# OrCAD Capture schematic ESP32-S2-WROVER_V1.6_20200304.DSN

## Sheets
1 01_DesignBlock: title: <ESP32-S2-WROVER>; rev: V1.6; note: <01_Design Block>
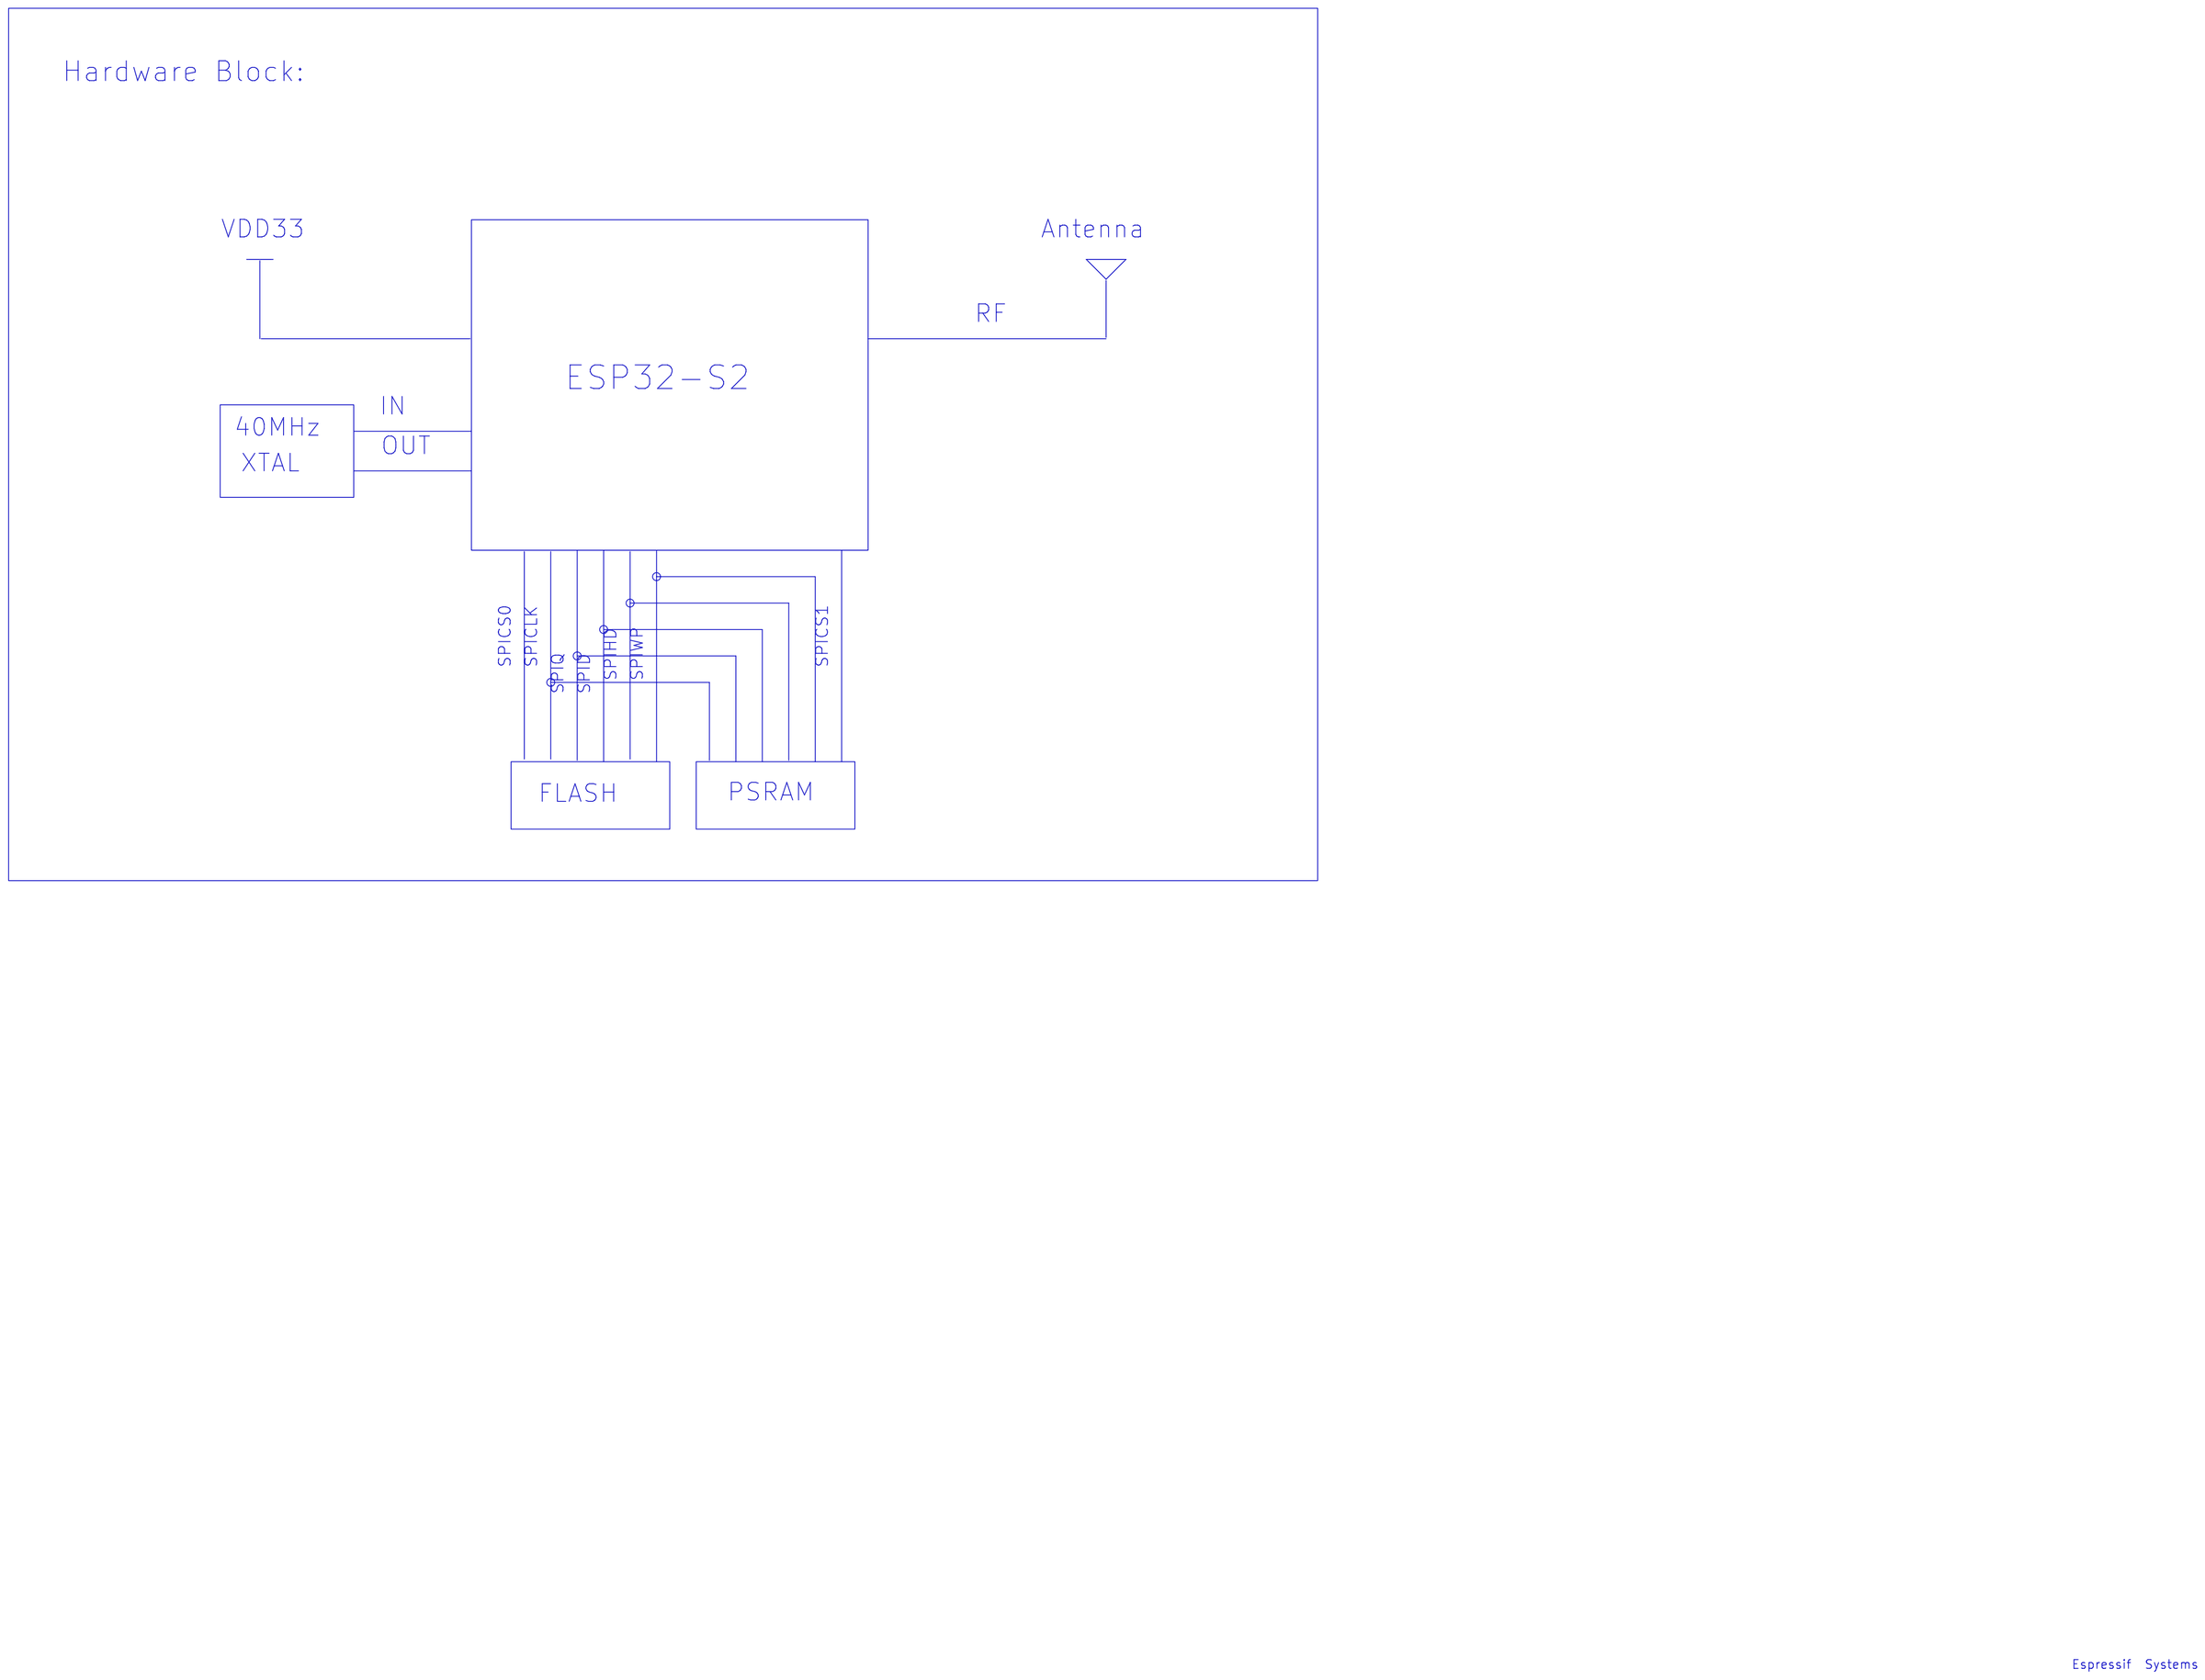
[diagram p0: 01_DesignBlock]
2 02_ESP32-S2-WROVER: size C; note: <02_ESP32-S2-WROVER>
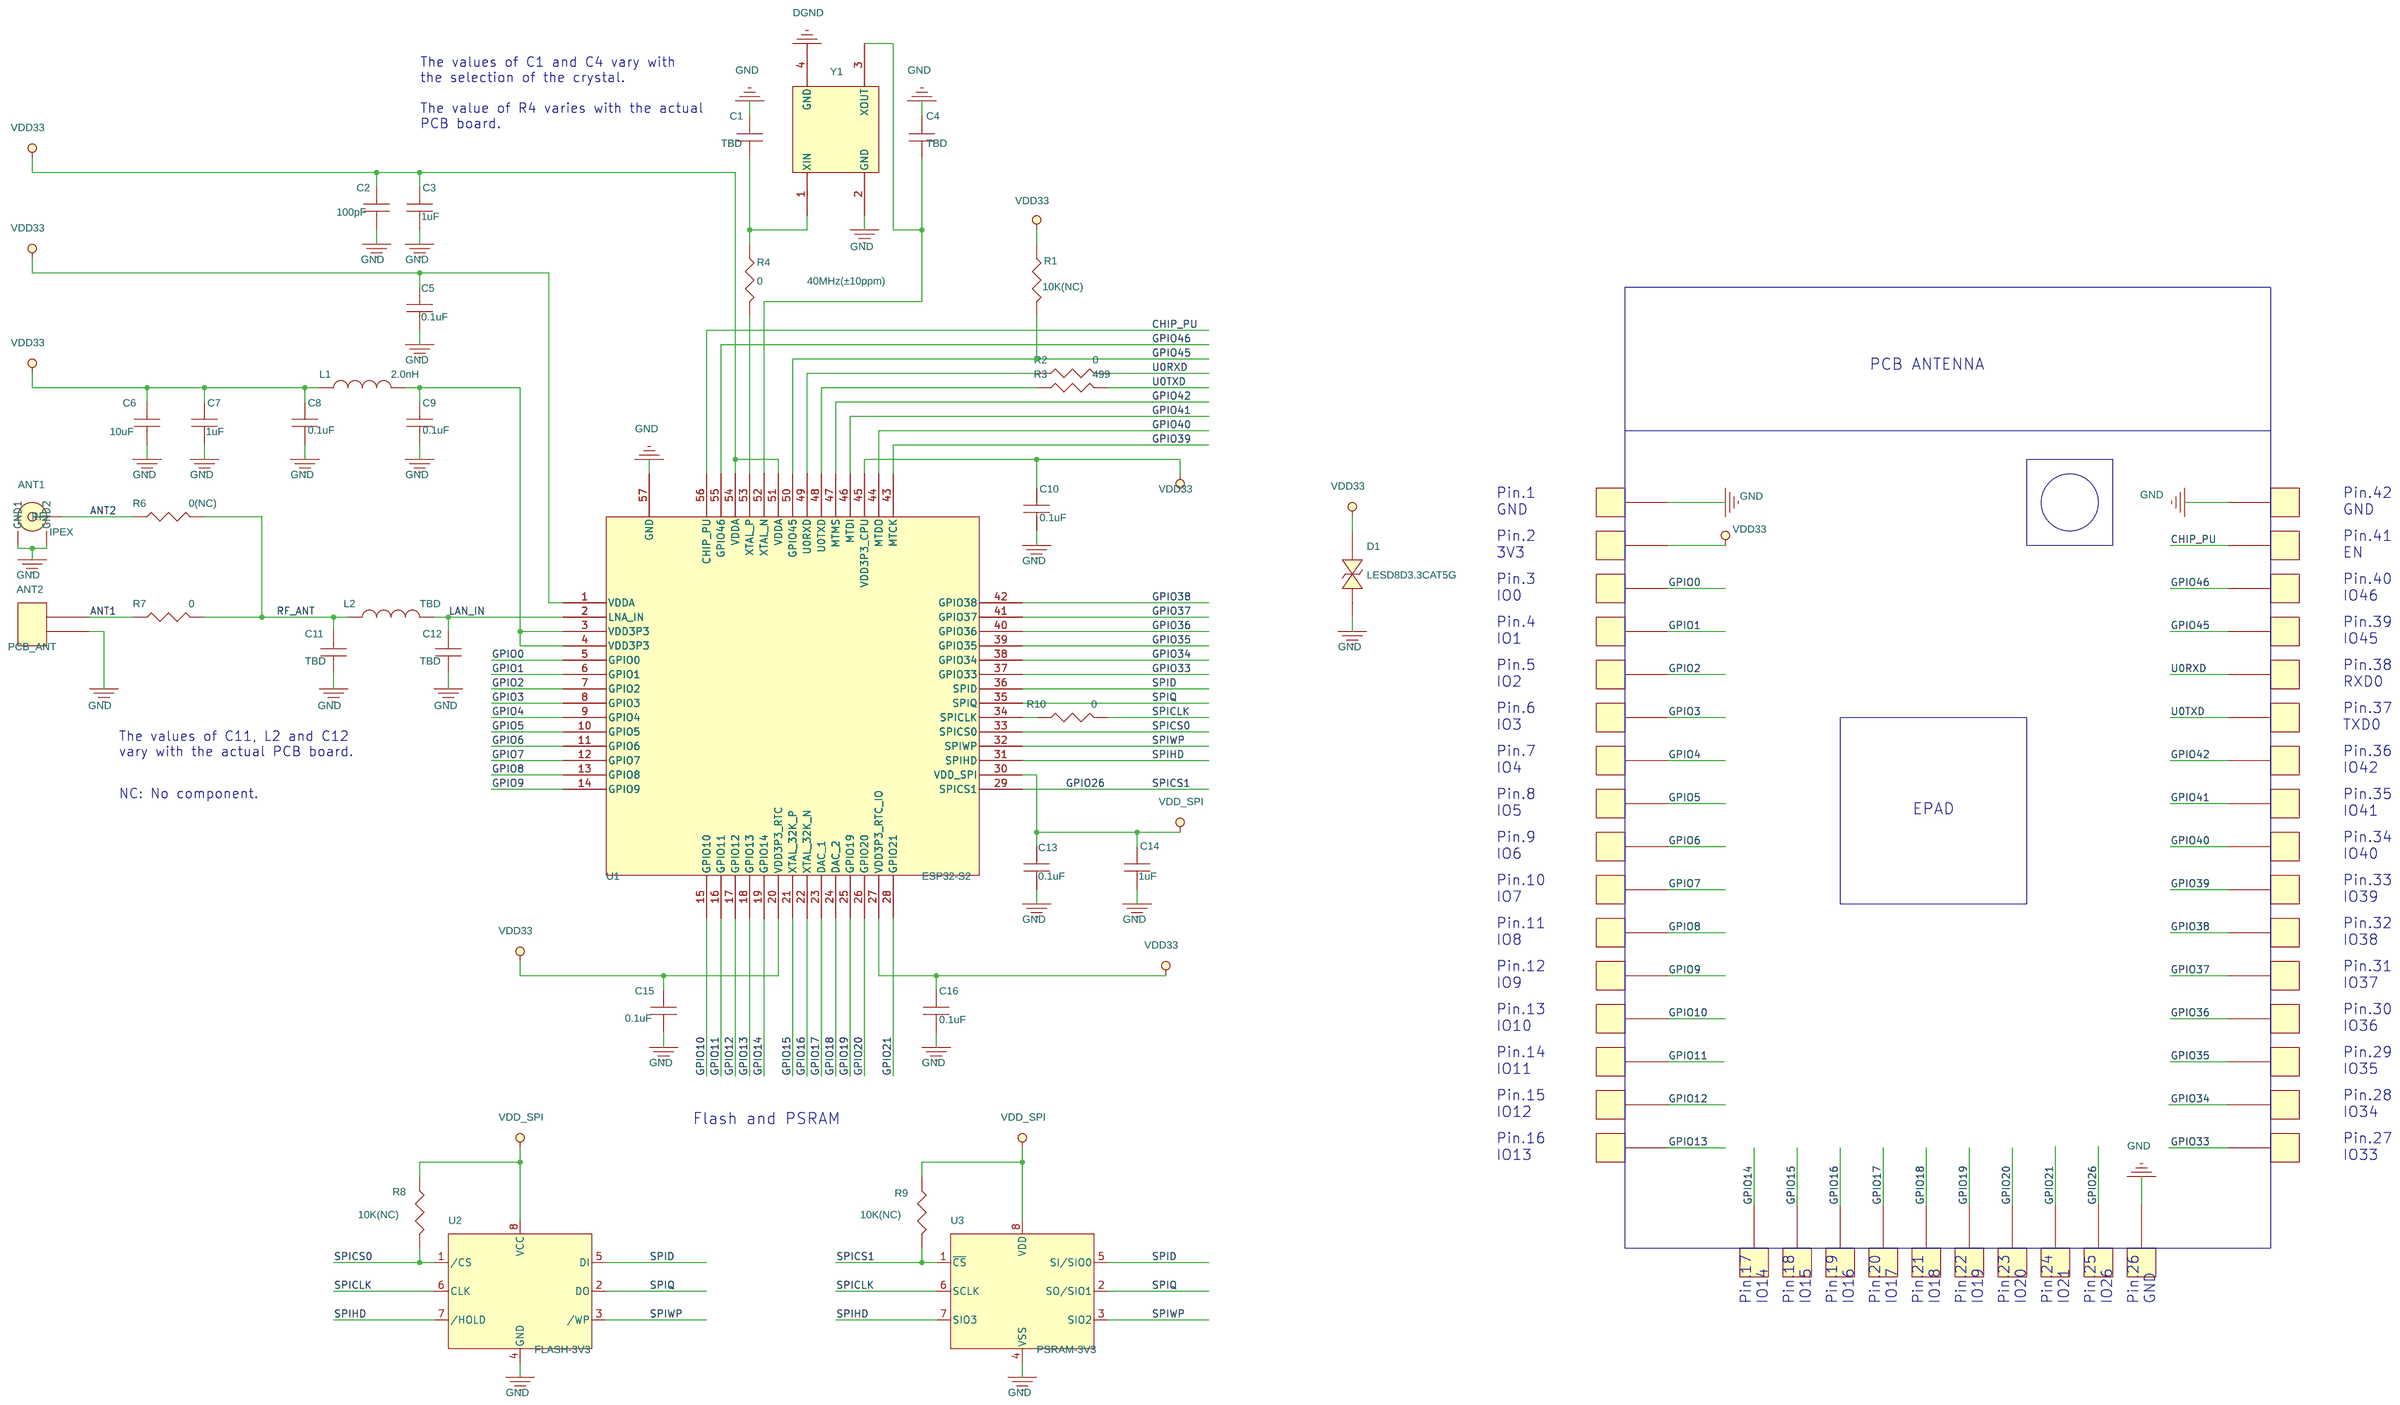
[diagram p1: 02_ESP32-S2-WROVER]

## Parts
ANT1  IPEX  [ECT818000368]
ANT2  PCB_ANT  [MINI_ANT_TYPEB]
C1  TBD  [C0201]
C2  100pF  [C0201]
C3  1uF  [C0201]
C4  TBD  [C0201]
C5  0.1uF  [C0201]
C6  10uF  [C0402]
C7  1uF  [C0201]
C8  0.1uF  [C0201]
C9  0.1uF  [C0201]
C10  0.1uF  [C0201]
C11  TBD  [C0201]
C12  TBD  [C0201]
C13  0.1uF  [C0201]
C14  1uF  [C0201]
C15  0.1uF  [C0201]
C16  0.1uF  [C0201]
D1  LESD8D3.3CAT5G  [SOD882]
J1  CON1  [SPAD_1]
J2  CON1  [SPAD_1]
J3  CON1  [SPAD_1]
J4  CON1  [SPAD_1]
J5  CON1  [SPAD_1]
J6  CON1  [SPAD_1]
J7  CON1  [SPAD_1]
J8  CON1  [SPAD_1]
J9  CON1  [SPAD_1]
J10  CON1  [SPAD_1]
J11  CON1  [SPAD_1]
J12  CON1  [SPAD_1]
J13  CON1  [SPAD_1]
J14  CON1  [SPAD_1]
J15  CON1  [SPAD_1]
J16  CON1  [SPAD_1]
J17  CON1  [SPAD_1]
J18  CON1  [SPAD_1]
J19  CON1  [SPAD_1]
J20  CON1  [SPAD_1]
J21  CON1  [SPAD_1]
J22  CON1  [SPAD_1]
J23  CON1  [SPAD_1]
J24  CON1  [SPAD_1]
J25  CON1  [SPAD_1]
J26  CON1  [SPAD_1]
J27  CON1  [SPAD_1]
J28  CON1  [SPAD_1]
J29  CON1  [SPAD_1]
J30  CON1  [SPAD_1]
J31  CON1  [SPAD_1]
J32  CON1  [SPAD_1]
J33  CON1  [SPAD_1]
J34  CON1  [SPAD_1]
J35  CON1  [SPAD_1]
J36  CON1  [SPAD_1]
J37  CON1  [SPAD_1]
J38  CON1  [SPAD_1]
J39  CON1  [SPAD_1]
J40  CON1  [SPAD_1]
J41  CON1  [SPAD_1]
J42  CON1  [SPAD_1]
L1  2.0nH  [L0201]
L2  TBD  [L0201]
R1  10K(NC)  [R0201]
R2  0  [R0201]
R3  499  [R0201]
R4  0  [R0201]
R6  0(NC)  [R0201A]
R7  0  [R0201A]
R8  10K(NC)  [R0201]
R9  10K(NC)  [R0201]
R10  0  [R0201]
U1  ESP32-S2  [QFN56_0P4_7]
U2  FLASH-3V3  [SOIC08-WN]
U3  PSRAM-3V3  [SOIC-8P]
Y1  40MHz(±10ppm)  [3225]

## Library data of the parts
ANT1 = IPEX_0
ANT2 = CON2
C1-C16 = CAP_NP
D1 = DIODE_BI-DIR_TRIG: Options: ESD
J1-J42 = CON1_1
L1 L2 = CHOKE
R1-R4 R6 R7 R10 = RESISTOR
R8 R9 = RESISTOR_0
U1 = ESP32K
U2 = FLASH_4
U3 = W25Q32_SOIC8_2
Y1 = X1_1

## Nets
GND: ANT1.2(GND1) ANT1.3(GND2) ANT2.2 C1.2 C2.2 C3.2 C4.2 C5.2 C6.2 C7.2 C8.2 C9.2 C10.2 C11.1 C12.1 C13.2 C14.2 C15.2 C16.2 D1.1 J1.1 J26.1 J42.1 U1.57(GND) U2.4(GND) U3.4(VSS) Y1.2(GND) Y1.4(GND)
VDD33: C2.1 C3.1 C5.1 C6.1 C7.1 C8.1 C10.1 C15.1 C16.1 D1.2 J2.1 L1.1 R1.1 U1.1(VDDA) U1.20(VDD3P3_RTC) U1.27(VDD3P3_RTC_IO) U1.45(VDD3P3_CPU) U1.51(VDDA) U1.54(VDDA)
VDD_SPI: C13.1 C14.1 R8.2 R9.2 U1.30(VDD_SPI) U2.8(VCC) U3.8(VDD)
ANT1: ANT2.1 R7.2
ANT2: ANT1.1(RF) R6.1
CHIP_PU: J41.1 U1.56(CHIP_PU)
GPIO0: J3.1 U1.5(GPIO0)
GPIO1: J4.1 U1.6(GPIO1)
GPIO2: J5.1 U1.7(GPIO2)
GPIO3: J6.1 U1.8(GPIO3)
GPIO4: J7.1 U1.9(GPIO4)
GPIO5: J8.1 U1.10(GPIO5)
GPIO6: J9.1 U1.11(GPIO6)
GPIO7: J10.1 U1.12(GPIO7)
GPIO8: J11.1 U1.13(GPIO8)
GPIO9: J12.1 U1.14(GPIO9)
GPIO10: J13.1 U1.15(GPIO10)
GPIO11: J14.1 U1.16(GPIO11)
GPIO12: J15.1 U1.17(GPIO12)
GPIO13: J16.1 U1.18(GPIO13)
GPIO14: J17.1 U1.19(GPIO14)
GPIO15: J18.1 U1.21(XTAL_32K_P)
GPIO16: J19.1 U1.22(XTAL_32K_N)
GPIO17: J20.1 U1.23(DAC_1)
GPIO18: J21.1 U1.24(DAC_2)
GPIO19: J22.1 U1.25(GPIO19)
GPIO20: J23.1 U1.26(GPIO20)
GPIO21: J24.1 U1.28(GPIO21)
GPIO26: J25.1 R9.1 U1.29(SPICS1) U3.1(~{CS})
GPIO33: J27.1 U1.37(GPIO33)
GPIO34: J28.1 U1.38(GPIO34)
GPIO35: J29.1 U1.39(GPIO35)
GPIO36: J30.1 U1.40(GPIO36)
GPIO37: J31.1 U1.41(GPIO37)
GPIO38: J32.1 U1.42(GPIO38)
GPIO39: J33.1 U1.43(MTCK)
GPIO40: J34.1 U1.44(MTDO)
GPIO41: J35.1 U1.46(MTDI)
GPIO42: J36.1 U1.47(MTMS)
GPIO45: J39.1 R1.2 U1.50(GPIO45)
GPIO46: J40.1 U1.55(GPIO46)
LAN_IN: C12.2 L2.1 U1.2(LNA_IN)
RF_ANT: C11.2 L2.2 R6.2 R7.1
SPICLK: R10.2 U2.6(CLK) U3.6(SCLK)
SPICS0: R8.1 U1.33(SPICS0) U2.1(/CS)
SPID: U1.36(SPID) U2.5(DI) U3.5(SI/SIO0)
SPIHD: U1.31(SPIHD) U2.7(/HOLD) U3.7(SIO3)
SPIQ: U1.35(SPIQ) U2.2(DO) U3.2(SO/SIO1)
SPIWP: U1.32(SPIWP) U2.3(/WP) U3.3(SIO2)
U0RXD: J38.1 R2.2
U0TXD: J37.1 R3.2
N16980501: R3.1 U1.48(U0TXD)
N16980531: R2.1 U1.49(U0RXD)
N16980759: R10.1 U1.34(SPICLK)
N16981224: C9.1 L1.2 U1.3(VDD3P3) U1.4(VDD3P3)
N16989795: C4.1 U1.52(XTAL_N) Y1.3(XOUT)
N16989829: C1.1 R4.1 Y1.1(XIN)
N16994903: R4.2 U1.53(XTAL_P)

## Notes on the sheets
sheet 1
- Hardware Block:
- VDD33
- Antenna
- RF
- ESP32-S2
- IN
- 40MHz
- OUT
- XTAL
- SPICS0
- SPICLK
- SPIHD
- SPIWP
- SPICS1
- SPIQ
- SPID
- FLASH
- PSRAM
- Espressif  Systems
sheet 2
- The values of C1 and C4 vary with
  the selection of the crystal.
  The value of R4 varies with the actual
  PCB board.
- PCB ANTENNA
- Pin.1
  GND
- Pin.42
  GND
- Pin.2
  3V3
- Pin.41
  EN
- Pin.3
  IO0
- Pin.40
  IO46
- Pin.4
  IO1
- Pin.39
  IO45
- Pin.5
  IO2
- Pin.38
  RXD0
- Pin.6
  IO3
- Pin.37
  TXD0
- The values of C11, L2 and C12
  vary with the actual PCB board.
- Pin.7
  IO4
- Pin.36
  IO42
- NC: No component.
- Pin.8
  IO5
- Pin.35
  IO41
- EPAD
- Pin.9
  IO6
- Pin.34
  IO40
- Pin.10
  IO7
- Pin.33
  IO39
- Pin.11
  IO8
- Pin.32
  IO38
- Pin.12
  IO9
- Pin.31
  IO37
- Pin.13
  IO10
- Pin.30
  IO36
- Pin.14
  IO11
- Pin.29
  IO35
- Pin.15
  IO12
- Pin.28
  IO34
- Flash and PSRAM
- Pin.16
  IO13
- Pin.27
  IO33
- Pin.17
  IO14
- Pin.18
  IO15
- Pin.19
  IO16
- Pin.20
  IO17
- Pin.21
  IO18
- Pin.22
  IO19
- Pin.23
  IO20
- Pin.24
  IO21
- Pin.25
  IO26
- Pin.26
  GND
